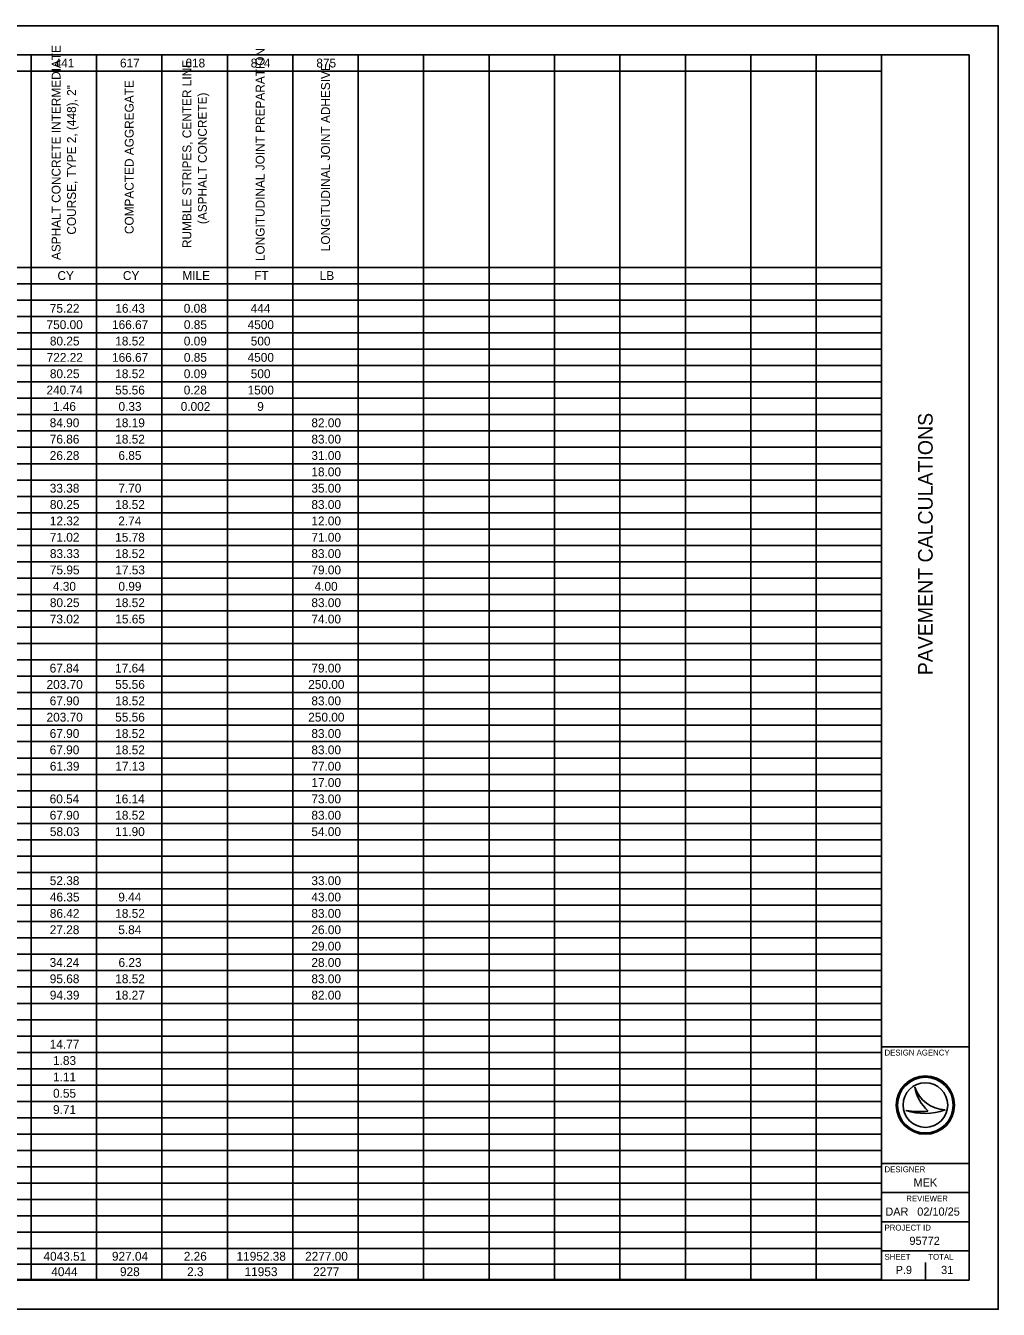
# Model space of a CAD drawing. Extents: x 0 to 34, y 0 to 22.
# Drawn here: x 17.33 to 34, y 0 to 22 of the extents above; entities that cross this region are included whole.
import ezdxf

# ---------------------------------------------------------------- set-up
doc = ezdxf.new("R2010")
doc.units = 0
for name, color, linetype in [('SH_Border', 7, 'Continuous'), ('SH_Cut_Line', 7, 'Continuous'), ('SH_Data', 7, 'Continuous'), ('SH_Text', 7, 'Continuous')]:
    doc.layers.add(name, color=color, linetype=linetype)

msp = doc.modelspace()

# ---------------------------------------------------------------- linework, layer by layer
at = {"layer": 'SH_Border'}
for p, q in [((32, 0.5), (32, 21.5)), ((32, 4.5), (33.5, 4.5)), ((32, 2.5), (33.5, 2.5)), ((32, 2), (33.5, 2)), ((32, 1.5), (33.5, 1.5)), ((32, 1), (33.5, 1))]:
    msp.add_line(p, q, dxfattribs=at)
msp.add_lwpolyline([(1.5, 21.5), (33.5, 21.5), (33.5, 0.5), (1.5, 0.5)], close=True, dxfattribs=at)
at = {"layer": 'SH_Cut_Line'}
msp.add_lwpolyline([(0, 0), (34, 0), (34, 22), (0, 22)], close=True, dxfattribs=at)
at = {"layer": 'SH_Data'}
for p, q in [((32.567, 3.81), (32.567, 3.81)), ((32.417, 3.41), (32.417, 3.41)), ((32.75, 3.5), (32.75, 3.5)), ((33.087, 3.419), (33.087, 3.419)), ((32.375, 0.675), (32.375, 0.675)), ((32.75, 0.5), (32.75, 0.8))]:
    msp.add_line(p, q, dxfattribs=at)
for radius in [0.5, 0.477, 0.477, 0.382]:
    msp.add_circle((32.75, 3.5), radius, dxfattribs=at)
for centre, radius, start, end in [((33.116, 3.998), 0.58, 198.9257, 198.9319), ((33.347, 3.97), 0.796, 191.6379, 191.6421), ((33.116, 3.998), 0.58, 198.9319, 267.1657), ((33.347, 3.97), 0.796, 191.6421, 226.0947), ((32.739, 4.37), 1.013, 251.4576, 290.0832), ((32.648, 4.654), 1.266, 259.4964, 259.4995), ((32.739, 4.37), 1.013, 251.4527, 251.4576), ((32.648, 4.654), 1.266, 259.4995, 276.6672)]:
    msp.add_arc(centre, radius, start, end, dxfattribs=at)
at = {"layer": 'SH_Text'}
for p, q in [((1.5, 21.5), (32, 21.5)), ((17.426, 21.5), (17.426, 0.513)), ((18.547, 21.5), (18.547, 0.513)), ((19.668, 21.5), (19.668, 0.513)), ((20.789, 21.5), (20.789, 0.513)), ((21.91, 21.5), (21.91, 0.513)), ((23.031, 21.5), (23.031, 0.513)), ((24.152, 21.5), (24.152, 0.513)), ((25.274, 21.5), (25.274, 0.513)), ((26.395, 21.5), (26.395, 0.513)), ((27.516, 21.5), (27.516, 0.513)), ((28.637, 21.5), (28.637, 0.513)), ((29.758, 21.5), (29.758, 0.513)), ((30.879, 21.5), (30.879, 0.513)), ((32, 21.5), (32, 0.513)), ((11.821, 21.22), (32, 21.22)), ((7.336, 17.856), (32, 17.856)), ((1.5, 17.576), (32, 17.576)), ((1.5, 17.296), (32, 17.296)), ((1.5, 17.016), (32, 17.016)), ((1.5, 16.735), (32, 16.735)), ((1.5, 16.455), (32, 16.455)), ((1.5, 16.175), (32, 16.175)), ((1.5, 15.895), (32, 15.895)), ((1.5, 15.614), (32, 15.614)), ((1.5, 15.334), (32, 15.334)), ((1.5, 15.054), (32, 15.054)), ((1.5, 14.774), (32, 14.774)), ((1.5, 14.493), (32, 14.493)), ((1.5, 14.213), (32, 14.213)), ((1.5, 13.933), (32, 13.933)), ((1.5, 13.652), (32, 13.652)), ((1.5, 13.372), (32, 13.372)), ((1.5, 13.092), (32, 13.092)), ((1.5, 12.812), (32, 12.812)), ((1.5, 12.531), (32, 12.531)), ((1.5, 12.251), (32, 12.251)), ((1.5, 11.971), (32, 11.971)), ((1.5, 11.691), (32, 11.691)), ((1.5, 11.41), (32, 11.41)), ((1.5, 11.13), (32, 11.13)), ((1.5, 10.85), (32, 10.85)), ((1.5, 10.569), (32, 10.569)), ((1.5, 10.289), (32, 10.289)), ((1.5, 10.009), (32, 10.009)), ((1.5, 9.729), (32, 9.729)), ((1.5, 9.448), (32, 9.448)), ((1.5, 9.168), (32, 9.168)), ((1.5, 8.888), (32, 8.888)), ((1.5, 8.608), (32, 8.608)), ((1.5, 8.327), (32, 8.327)), ((1.5, 8.047), (32, 8.047)), ((1.5, 7.767), (32, 7.767)), ((1.5, 7.486), (32, 7.486)), ((1.5, 7.206), (32, 7.206)), ((1.5, 6.926), (32, 6.926)), ((1.5, 6.646), (32, 6.646)), ((1.5, 6.365), (32, 6.365)), ((1.5, 6.085), (32, 6.085)), ((1.5, 5.805), (32, 5.805)), ((1.5, 5.525), (32, 5.525)), ((1.5, 5.244), (32, 5.244)), ((1.5, 4.964), (32, 4.964)), ((1.5, 4.684), (32, 4.684)), ((1.5, 4.404), (32, 4.404)), ((1.5, 4.123), (32, 4.123)), ((1.5, 3.843), (32, 3.843)), ((1.5, 3.563), (32, 3.563)), ((1.5, 3.282), (32, 3.282)), ((1.5, 3.002), (32, 3.002)), ((1.5, 2.722), (32, 2.722)), ((1.5, 2.442), (32, 2.442)), ((1.5, 2.161), (32, 2.161)), ((1.5, 1.881), (32, 1.881)), ((1.5, 1.601), (32, 1.601)), ((1.5, 1.321), (32, 1.321)), ((1.5, 1.04), (32, 1.04)), ((1.5, 0.776), (32, 0.776)), ((1.5, 0.513), (32, 0.513))]:
    msp.add_line(p, q, dxfattribs=at)

# ---------------------------------------------------------------- texts
at = {"layer": 'SH_Data'}
msp.add_text('PAVEMENT CALCULATIONS', height=0.25, rotation=90, dxfattribs=at).set_placement((32.875, 10.868))
for s, height, p in [('DESIGN AGENCY', 0.1, (32.05, 4.35)), ('DESIGNER', 0.1, (32.05, 2.35)), ('MEK', 0.14, (32.547, 2.105)), ('REVIEWER', 0.1, (32.422, 1.85)), ('DAR', 0.14, (32.064, 1.605)), ('02/10/25', 0.14, (32.611, 1.605)), ('PROJECT ID', 0.1, (32.05, 1.35)), ('95772', 0.14, (32.477, 1.105)), ('SHEET', 0.1, (32.05, 0.85)), ('TOTAL', 0.1, (32.8, 0.85)), ('P.9', 0.14, (32.24, 0.605)), ('31', 0.14, (33.019, 0.605))]:
    msp.add_text(s, height=height, dxfattribs=at).set_placement(p)
at = {"layer": 'SH_Text'}
for s, p in [('ASPHALT CONCRETE INTERMEDIATE ', (17.93, 17.983)), ('LONGITUDINAL JOINT PREPARATION', (21.426, 17.966)), ('RUMBLE STRIPES, CENTER LINE ', (20.172, 18.189)), ('LONGITUDINAL JOINT ADHESIVE', (22.547, 18.134)), ('COURSE, TYPE 2, (448), 2"', (18.195, 18.419)), ('COMPACTED AGGREGATE', (19.183, 18.428)), ('(ASPHALT CONCRETE)', (20.437, 18.599))]:
    msp.add_text(s, height=0.15168, rotation=90, dxfattribs=at).set_placement(p)
for s, height, p in [('441', 0.1517, (17.829, 21.284)), ('617', 0.1517, (18.949, 21.284)), ('618', 0.1517, (20.07, 21.284)), ('874', 0.1517, (21.189, 21.284)), ('875', 0.1517, (22.314, 21.284)), ('CY', 0.1517, (17.878, 17.641)), ('CY', 0.1517, (18.999, 17.641)), ('MILE', 0.1517, (20.018, 17.641)), ('FT', 0.1517, (21.249, 17.641)), ('LB', 0.1517, (22.372, 17.641)), ('75.22', 0.1517, (17.747, 17.08)), ('16.43', 0.1517, (18.869, 17.08)), ('0.08', 0.1517, (20.042, 17.08)), ('444', 0.1517, (21.189, 17.08)), ('750.00', 0.1517, (17.691, 16.8)), ('166.67', 0.1517, (18.813, 16.8)), ('0.85', 0.1517, (20.044, 16.8)), ('4500', 0.1517, (21.136, 16.8)), ('80.25', 0.1517, (17.748, 16.519)), ('18.52', 0.1517, (18.868, 16.519)), ('0.09', 0.1517, (20.043, 16.519)), ('500', 0.1517, (21.19, 16.519)), ('722.22', 0.1517, (17.693, 16.239)), ('166.67', 0.1517, (18.813, 16.239)), ('0.85', 0.1517, (20.044, 16.239)), ('4500', 0.1517, (21.136, 16.239)), ('80.25', 0.1517, (17.748, 15.959)), ('18.52', 0.1517, (18.868, 15.959)), ('0.09', 0.1517, (20.043, 15.959)), ('500', 0.1517, (21.19, 15.959)), ('240.74', 0.1517, (17.69, 15.679)), ('55.56', 0.1517, (18.867, 15.679)), ('0.28', 0.1517, (20.042, 15.679)), ('1500', 0.1517, (21.136, 15.679)), ('1.46', 0.1517, (17.8, 15.398)), ('0.33', 0.1517, (18.924, 15.398)), ('0.002', 0.1517, (19.99, 15.398)), ('9', 0.152, (21.301, 15.398)), ('84.90', 0.1517, (17.745, 15.118)), ('18.19', 0.1517, (18.868, 15.118)), ('82.00', 0.1517, (22.229, 15.118)), ('76.86', 0.1517, (17.746, 14.838)), ('18.52', 0.1517, (18.868, 14.838)), ('83.00', 0.1517, (22.229, 14.838)), ('26.28', 0.1517, (17.746, 14.558)), ('6.85', 0.1517, (18.923, 14.558)), ('31.00', 0.1517, (22.229, 14.558)), ('18.00', 0.1517, (22.229, 14.277)), ('33.38', 0.1517, (17.746, 13.997)), ('7.70', 0.1517, (18.921, 13.997)), ('35.00', 0.1517, (22.229, 13.997)), ('80.25', 0.1517, (17.748, 13.717)), ('18.52', 0.1517, (18.868, 13.717)), ('83.00', 0.1517, (22.229, 13.717)), ('12.32', 0.1517, (17.747, 13.436)), ('2.74', 0.1517, (18.92, 13.436)), ('12.00', 0.1517, (22.229, 13.436)), ('71.02', 0.1517, (17.747, 13.156)), ('15.78', 0.1517, (18.867, 13.156)), ('71.00', 0.1517, (22.229, 13.156)), ('83.33', 0.1517, (17.748, 12.876)), ('18.52', 0.1517, (18.868, 12.876)), ('83.00', 0.1517, (22.229, 12.876)), ('75.95', 0.1517, (17.748, 12.596)), ('17.53', 0.1517, (18.869, 12.596)), ('79.00', 0.1517, (22.229, 12.596)), ('4.30', 0.1517, (17.8, 12.315)), ('0.99', 0.1517, (18.922, 12.315)), ('4.00', 0.1517, (22.284, 12.315)), ('80.25', 0.1517, (17.748, 12.035)), ('18.52', 0.1517, (18.868, 12.035)), ('83.00', 0.1517, (22.229, 12.035)), ('73.02', 0.1517, (17.747, 11.755)), ('15.65', 0.1517, (18.869, 11.755)), ('74.00', 0.1517, (22.229, 11.755)), ('67.84', 0.1517, (17.744, 10.914)), ('17.64', 0.1517, (18.866, 10.914)), ('79.00', 0.1517, (22.229, 10.914)), ('203.70', 0.1517, (17.691, 10.634)), ('55.56', 0.1517, (18.867, 10.634)), ('250.00', 0.1517, (22.175, 10.634)), ('67.90', 0.1517, (17.745, 10.353)), ('18.52', 0.1517, (18.868, 10.353)), ('83.00', 0.1517, (22.229, 10.353)), ('203.70', 0.1517, (17.691, 10.073)), ('55.56', 0.1517, (18.867, 10.073)), ('250.00', 0.1517, (22.175, 10.073)), ('67.90', 0.1517, (17.745, 9.793)), ('18.52', 0.1517, (18.868, 9.793)), ('83.00', 0.1517, (22.229, 9.793)), ('67.90', 0.1517, (17.745, 9.513)), ('18.52', 0.1517, (18.868, 9.513)), ('83.00', 0.1517, (22.229, 9.513)), ('61.39', 0.1517, (17.747, 9.232)), ('17.13', 0.1517, (18.869, 9.232)), ('77.00', 0.1517, (22.229, 9.232)), ('17.00', 0.1517, (22.229, 8.952)), ('60.54', 0.1517, (17.744, 8.672)), ('16.14', 0.1517, (18.866, 8.672)), ('73.00', 0.1517, (22.229, 8.672)), ('67.90', 0.1517, (17.745, 8.392)), ('18.52', 0.1517, (18.868, 8.392)), ('83.00', 0.1517, (22.229, 8.392)), ('58.03', 0.1517, (17.748, 8.111)), ('11.90', 0.1517, (18.866, 8.111)), ('54.00', 0.1517, (22.229, 8.111)), ('52.38', 0.1517, (17.746, 7.271)), ('33.00', 0.1517, (22.229, 7.271)), ('46.35', 0.1517, (17.748, 6.99)), ('9.44', 0.1517, (18.92, 6.99)), ('43.00', 0.1517, (22.229, 6.99)), ('86.42', 0.1517, (17.747, 6.71)), ('18.52', 0.1517, (18.868, 6.71)), ('83.00', 0.1517, (22.229, 6.71)), ('27.28', 0.1517, (17.746, 6.43)), ('5.84', 0.1517, (18.92, 6.43)), ('26.00', 0.1517, (22.229, 6.43)), ('29.00', 0.1517, (22.229, 6.149)), ('34.24', 0.1517, (17.744, 5.869)), ('6.23', 0.1517, (18.924, 5.869)), ('28.00', 0.1517, (22.229, 5.869)), ('95.68', 0.1517, (17.746, 5.589)), ('18.52', 0.1517, (18.868, 5.589)), ('83.00', 0.1517, (22.229, 5.589)), ('94.39', 0.1517, (17.747, 5.309)), ('18.27', 0.1517, (18.867, 5.309)), ('82.00', 0.1517, (22.229, 5.309)), ('14.77', 0.1517, (17.746, 4.468)), ('1.83', 0.1517, (17.802, 4.188)), ('1.11', 0.1517, (17.802, 3.907)), ('0.55', 0.1517, (17.802, 3.627)), ('9.71', 0.1517, (17.802, 3.347)), ('4043.51', 0.1517, (17.638, 0.833)), ('927.04', 0.1517, (18.811, 0.833)), ('2.26', 0.1517, (20.042, 0.833)), ('11952.38', 0.1517, (20.946, 0.833)), ('2277.00', 0.1517, (22.121, 0.833)), ('4044', 0.1517, (17.772, 0.569)), ('928', 0.1517, (18.949, 0.569)), ('2.3', 0.1517, (20.099, 0.569)), ('11953', 0.1517, (21.084, 0.569)), ('2277', 0.1517, (22.258, 0.569))]:
    msp.add_text(s, height=height, dxfattribs=at).set_placement(p)

doc.saveas('drawing.dxf')
